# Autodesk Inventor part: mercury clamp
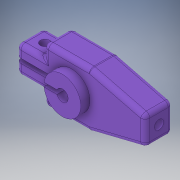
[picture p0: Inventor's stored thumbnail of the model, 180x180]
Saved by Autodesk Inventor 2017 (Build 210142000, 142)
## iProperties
Created: 2016-05
Part Number: mercury clamp
Material: Generic
Document SubType Name: Modeling
Designer: Stan
Density: 1 g/cm^3
Appearance: Violet
Author: Stan
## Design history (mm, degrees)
sketch "Sketch1"
  geometry: L1 (-9.525, 9.525)-(6.35, 9.525); L2 (6.35, -9.463)-(-9.525, -9.463); L3 (25.4, 4.763)-(25.4, -4.763); L4 (25.4, -4.763)-(6.35, -9.463); L5 (25.4, 4.763)-(6.35, 9.525); L6 (-9.525, 9.525)-(-9.525, 4.763); L7 (-9.525, 4.763)-(-19.05, 4.762); L8 (-19.05, -4.7)-(-9.525, -4.7); L9 (-9.525, -4.7)-(-9.525, -9.463); L10 (-1.832, 0.762)-(-19.05, 0.762); L11 (-1.832, -0.762)-(-19.05, -0.762); L12 (-19.05, -4.7)-(-19.05, -0.762); L13 (-19.05, 0.762)-(-19.05, 4.762); A1 r 1.984 centre (0, 0) between (-1.832, -0.762) and (-1.832, 0.762); 1 further point
  constraints: 26 end point, 4 perpendicular, 2 point on circle, 2 point on line, 2 vertical, 1 centre point, 1 coincident, 1 horizontal, 1 parallel
  dimensions: "d1" = 9.525 distance from line of L1 point (0, 0); "d2" = 25.4 horizontal distance of L3.end point (0, 0); "d4" = 9.525 distance of L3.start L3.end; "d5" = 4.7625 vertical distance of point (0, 0) L3.start; "d7" = 3.96875 diameter of A1; "d8" = 19.05 horizontal distance of L8.start point (0, 0); "d11" = 9.525 distance from line of point (0, 0) L6; "d12" = 19.05 distance from line of point (0, 0) L13; "d14" = 1.524 distance between parallel lines of L11 L10; "d15" = 0.762 distance from line of L10 point (0, 0); "d16" = 15.875 distance of L1.start L1.end; "d17" = 15.875 distance of L2.start L2.end; "d18" = 4.7625 distance between parallel lines of L2 L8; "d19" = 4.7625 distance between parallel lines of L7 L1
extrude "Extrusion1" new body sketch "Sketch1" distance "d20" = 9.525; taper "d21" = 0 deg
fillet "Fillet1" dims "d22" = 1.5875
sketch "Sketch2"
  geometry: C1 r 1.587 at (3.175, 3.519); 1 further point
  constraints: 1 centre point
  dimensions: "d23" = 3.175 diameter of C1
extrude "Extrusion2" cut sketch "Sketch2" distance "d24" = 15.875; taper "d25" = 0 deg
sketch "Sketch3"
  geometry: L1 (-1.587, 6.35)-(-1.588, 0) reference; C1 r 1.587 at (3.492, 3.175); 1 further point
  constraints: 1 centre point
  dimensions: "d26" = 3.175 diameter of C1; "d27" = 5.08 distance from line of C1.centre L1
extrude "Extrusion3" cut sketch "Sketch3" distance "d28" = 9.525; taper "d29" = 0 deg
fillet "Fillet2" dims "d30" = 1.5875
fillet "Fillet3" dims "d31" = 1.5875
sketch "Sketch4"
  geometry: L1 (-1.832, 0.762)-(-6.304, 0.762); L2 (-17.462, 0.762)-(-1.832, 0.762) reference; L3 (-1.88, -0.635)-(-6.318, -0.635); A1 r 6.35 centre (0, 0) between (-6.318, -0.635) and (-6.304, 0.762); A2 r 1.984 centre (0, 0) between (-1.88, -0.635) and (-1.832, 0.762); 1 further point
  constraints: 5 end point, 4 point on circle, 2 centre point, 2 coincident, 1 parallel, 1 point on line
  dimensions: "d32" = 12.7 diameter of A1
extrude "Extrusion4" join sketch "Sketch4" distance "d33" = 3.175; taper "d34" = 0 deg
body "Solid1"
